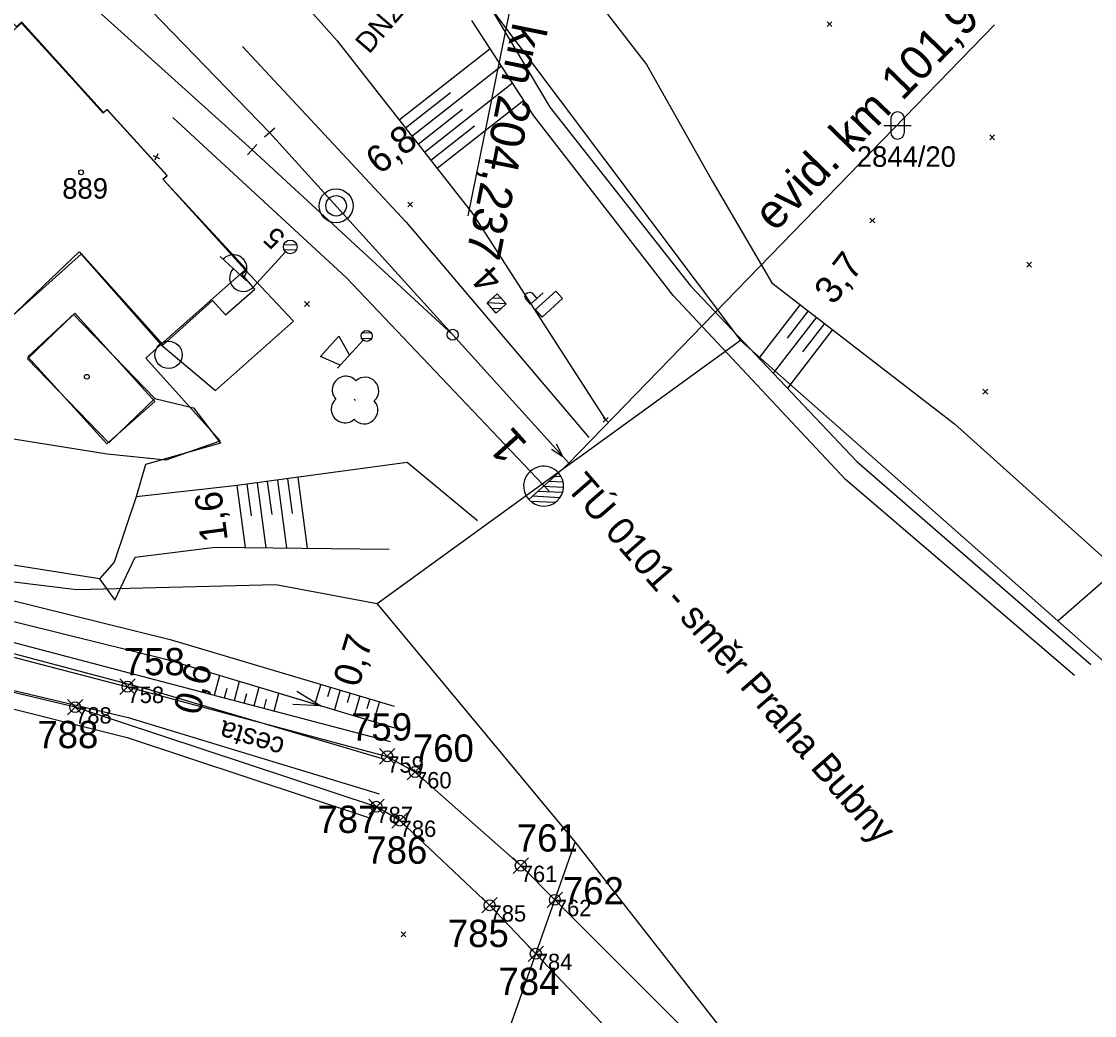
# Model space of a CAD drawing. Extents: x -800194 to -799078, y -1007177 to -1006597.
# Drawn here: x -799753.2 to -799674.6, y -1007080.7 to -1007007.9 of the extents above; entities that cross this region are included whole.
import ezdxf

# ---------------------------------------------------------------- set-up
doc = ezdxf.new("R2010")
doc.units = 0
for name, color, linetype in [('02_Osa_koleje', 7, 'Continuous'), ('_návrh', 7, 'Continuous'), ('Obvod stavby', 7, 'Continuous'), ('Vrstva 11', 7, 'Continuous'), ('Vrstva 13', 7, 'Continuous'), ('Vrstva 17', 7, 'Continuous'), ('Vrstva 2', 7, 'Continuous'), ('Vrstva 23', 7, 'Continuous'), ('Vrstva 25', 7, 'Continuous'), ('Vrstva 33', 7, 'Continuous'), ('Vrstva 4', 7, 'Continuous'), ('Vrstva 43', 7, 'Continuous'), ('Vrstva 48', 7, 'Continuous'), ('Vrstva 49', 7, 'Continuous'), ('Vrstva 5', 7, 'Continuous'), ('Vrstva 50', 7, 'Continuous'), ('Vrstva 51', 7, 'Continuous'), ('Vrstva 55', 7, 'Continuous'), ('Vrstva 56', 7, 'Continuous'), ('Vrstva 57', 7, 'Continuous'), ('Vrstva 58', 7, 'Continuous'), ('Vrstva 59', 7, 'Continuous'), ('Vrstva 60', 7, 'Continuous'), ('Vrstva 7', 7, 'Continuous')]:
    doc.layers.add(name, color=color, linetype=linetype)

msp = doc.modelspace()

# ---------------------------------------------------------------- linework, layer by layer
at = {"layer": '_návrh'}
for points in [[(-799821.595, -1006948.007), (-799811.064, -1006954.324), (-799803.753, -1006958.707), (-799793.935, -1006964.581), (-799784.224, -1006971.671), (-799782.913, -1006972.63), (-799767.418, -1006984.719), (-799752.333, -1006998.173), (-799735.027, -1007015.997), (-799721.623, -1007030.81), (-799713.555, -1007039.726), (-799713.111, -1007040.218)], [(-799820.755, -1006954.001), (-799803.004, -1006964.743), (-799786.682, -1006975.322), (-799769.882, -1006987.807), (-799754.745, -1007000.643), (-799736.311, -1007017.261), (-799721.623, -1007030.81)]]:
    msp.add_lwpolyline(points, dxfattribs=at)
at = {"layer": 'Obvod stavby'}
for p, q in [((-799746.003, -1007057.146), (-799744.871, -1007056.015)), ((-799746.003, -1007056.015), (-799744.871, -1007057.146)), ((-799749.839, -1007058.649), (-799748.707, -1007057.517)), ((-799749.839, -1007057.517), (-799748.707, -1007058.649)), ((-799726.983, -1007062.246), (-799725.851, -1007061.115)), ((-799726.983, -1007061.115), (-799725.851, -1007062.246)), ((-799724.949, -1007063.392), (-799723.818, -1007062.261)), ((-799724.949, -1007062.261), (-799723.818, -1007063.392)), ((-799727.776, -1007065.938), (-799726.645, -1007064.807)), ((-799727.776, -1007064.807), (-799726.645, -1007065.938)), ((-799726.072, -1007066.948), (-799724.941, -1007065.817)), ((-799726.072, -1007065.817), (-799724.941, -1007066.948)), ((-799717.202, -1007070.252), (-799716.071, -1007069.121)), ((-799717.202, -1007069.121), (-799716.071, -1007070.252)), ((-799719.487, -1007073.148), (-799718.356, -1007072.016)), ((-799719.487, -1007072.016), (-799718.356, -1007073.148)), ((-799714.706, -1007072.751), (-799713.575, -1007071.619)), ((-799714.706, -1007071.619), (-799713.575, -1007072.751)), ((-799716.104, -1007076.702), (-799714.973, -1007075.571)), ((-799716.104, -1007075.571), (-799714.973, -1007076.702))]:
    msp.add_line(p, q, dxfattribs=at)
for points in [[(-799715.538, -1007076.136), (-799718.921, -1007072.582), (-799725.506, -1007066.383), (-799727.21, -1007065.372), (-799749.273, -1007058.083), (-799778.375, -1007051.157), (-799786.694, -1007048.305), (-799789.278, -1007046.386), (-799797.841, -1007037.951)], [(-799788.573, -1007041.596), (-799787.358, -1007042.812), (-799784.876, -1007044.993), (-799778.248, -1007048.055), (-799745.437, -1007056.58), (-799726.417, -1007061.681), (-799724.384, -1007062.827), (-799716.636, -1007069.686), (-799714.141, -1007072.185)], [(-799715.538, -1007076.136), (-799696.398, -1007096.249), (-799680.349, -1007116.924), (-799673.33, -1007118.14), (-799693.106, -1007093.246), (-799714.141, -1007072.185)]]:
    msp.add_lwpolyline(points, dxfattribs=at)
for centre in [(-799745.437, -1007056.58), (-799749.273, -1007058.083), (-799726.417, -1007061.681), (-799724.384, -1007062.827), (-799727.21, -1007065.372), (-799725.506, -1007066.383), (-799716.636, -1007069.686), (-799714.141, -1007072.185), (-799718.921, -1007072.582), (-799715.538, -1007076.136)]:
    msp.add_circle(centre, 0.4, dxfattribs=at)
at = {"layer": 'Vrstva 11'}
for p, q in [((-799717.697, -1007028.557), (-799719.105, -1007028.487)), ((-799718.048, -1007028.164), (-799718.716, -1007028.131)), ((-799718.09, -1007028.913), (-799718.75, -1007028.88))]:
    msp.add_line(p, q, dxfattribs=at)
msp.add_lwpolyline([(-799718.436, -1007029.226), (-799719.107, -1007028.485), (-799718.366, -1007027.814), (-799717.695, -1007028.555)], close=True, dxfattribs=at)
at = {"layer": 'Vrstva 13'}
msp.add_line((-799737.018, -1007056.245), (-799731.272, -1007057.973), dxfattribs=at)
for points in [[(-799805.067, -1007021.457), (-799784.005, -1007043.381), (-799779.029, -1007045.556), (-799742.637, -1007054.554), (-799725.892, -1007059.592)], [(-799733.043, -1007056.918), (-799731.272, -1007057.973), (-799733.331, -1007057.876)]]:
    msp.add_lwpolyline(points, dxfattribs=at)
at = {"layer": 'Vrstva 17'}
msp.add_line((-799738.616, -1007038.761), (-799744.108, -1007040.301), dxfattribs=at)
for points in [[(-799828.95, -1007006.881), (-799820.579, -1007016.712), (-799786.808, -1007048.821), (-799777.641, -1007052.247), (-799745.452, -1007060.292), (-799727.709, -1007066.187)], [(-799744.108, -1007040.301), (-799744.795, -1007042.69), (-799746.422, -1007047.465), (-799747.487, -1007048.694), (-799771.226, -1007044.934), (-799785.53, -1007035.198), (-799789.014, -1007035.746), (-799804.246, -1007020.27), (-799801.55, -1007019.072), (-799803.933, -1007010.185)], [(-799743.447, -1007035.487), (-799740.602, -1007036.154), (-799738.616, -1007038.761)]]:
    msp.add_lwpolyline(points, dxfattribs=at)
at = {"layer": 'Vrstva 2'}
for p, q in [((-799713.111, -1007040.218), (-799681.94, -1007008.129)), ((-799735.398, -1007016.332), (-799734.656, -1007015.662)), ((-799735.972, -1007016.893), (-799736.65, -1007017.629)), ((-799713.88, -1007040.917), (-799713.111, -1007040.218)), ((-799716.05, -1007042.881), (-799713.879, -1007040.917)), ((-799713.668, -1007041.225), (-799714.191, -1007041.199)), ((-799713.508, -1007041.994), (-799714.989, -1007041.92)), ((-799713.532, -1007041.613), (-799714.59, -1007041.56)), ((-799716.05, -1007042.881), (-799716.05, -1007042.881)), ((-799713.772, -1007042.742), (-799715.786, -1007042.641)), ((-799713.582, -1007042.371), (-799715.388, -1007042.281)), ((-799714.138, -1007043.104), (-799715.906, -1007043.016))]:
    msp.add_line(p, q, dxfattribs=at)
msp.add_lwpolyline([(-799714.395, -1007039.183), (-799713.555, -1007039.726), (-799714.011, -1007038.836)], dxfattribs=at)
msp.add_circle((-799721.623, -1007030.81), 0.4, dxfattribs=at)
for centre, radius, start, end in [((-799714.965, -1007041.897), 1.462, 42.07181, 222.54133), ((-799714.964, -1007041.899), 1.464, 222.16134, 42.12219)]:
    msp.add_arc(centre, radius, start, end, dxfattribs=at)
at = {"layer": 'Vrstva 23'}
for points in [[(-799756.701, -1007031.945), (-799748.818, -1007024.882), (-799742.835, -1007031.56), (-799739.203, -1007028.306), (-799738.261, -1007029.357), (-799736.112, -1007027.467), (-799737.076, -1007026.37), (-799736.711, -1007026.049), (-799742.825, -1007019.446), (-799742.529, -1007019.177), (-799746.942, -1007014.309), (-799747.197, -1007014.54), (-799753.188, -1007007.931), (-799753.56, -1007008.268), (-799754.56, -1007007.163), (-799756.669, -1007009.071), (-799755.683, -1007010.172), (-799759.339, -1007013.448), (-799754.227, -1007019.154), (-799755.62, -1007020.402), (-799754.738, -1007021.386), (-799761.075, -1007027.063), (-799756.701, -1007031.945)], [(-799746.801, -1007038.734), (-799743.447, -1007035.487), (-799749.396, -1007029.332), (-799752.758, -1007032.581), (-799746.801, -1007038.734)]]:
    msp.add_lwpolyline(points, dxfattribs=at)
at = {"layer": 'Vrstva 25'}
for p, q in [((-799733.856, -1007024.746), (-799736.228, -1007027.319)), ((-799733.045, -1007024.219), (-799734.002, -1007024.258)), ((-799733.067, -1007024.595), (-799733.945, -1007024.63)), ((-799736.743, -1007026.845), (-799738.654, -1007025.083))]:
    msp.add_line(p, q, dxfattribs=at)
msp.add_circle((-799733.517, -1007024.378), 0.5, dxfattribs=at)
for centre, start, end in [((-799737.69, -1007025.955), 316.63315, 138.0383), ((-799736.963, -1007026.642), 137.33573, 317.33573)]:
    msp.add_arc(centre, 1, start, end, dxfattribs=at)
at = {"layer": 'Vrstva 33'}
for p, q in [((-799731.306, -1007032.395), (-799729.951, -1007030.925)), ((-799729.951, -1007030.925), (-799729.187, -1007032.309)), ((-799727.589, -1007030.677), (-799728.27, -1007030.705)), ((-799727.564, -1007031.076), (-799728.259, -1007031.105)), ((-799730.068, -1007033.265), (-799728.175, -1007031.207)), ((-799729.865, -1007033.044), (-799731.306, -1007032.395))]:
    msp.add_line(p, q, dxfattribs=at)
for points in [[(-799716.268, -1007028.193), (-799716.335, -1007028.041), (-799716.259, -1007027.823), (-799716.177, -1007027.748), (-799715.949, -1007027.691), (-799715.809, -1007027.778)], [(-799714.988, -1007027.738), (-799715.918, -1007028.58)], [(-799715.809, -1007027.778), (-799715.459, -1007028.164)], [(-799715.918, -1007028.58), (-799716.268, -1007028.193)]]:
    msp.add_lwpolyline(points, dxfattribs=at)
msp.add_lwpolyline([(-799715.065, -1007029.516), (-799715.565, -1007028.964), (-799714.071, -1007027.612), (-799713.571, -1007028.164)], close=True, dxfattribs=at)
msp.add_circle((-799727.921, -1007030.897), 0.401, dxfattribs=at)
at = {"layer": 'Vrstva 4'}
for points in [[(-799737.021, -1007009.695), (-799725.033, -1007022.564), (-799711.647, -1007038.333)], [(-799742.121, -1007014.91), (-799729.412, -1007026.634), (-799714.559, -1007042.274)]]:
    msp.add_lwpolyline(points, dxfattribs=at)
at = {"layer": 'Vrstva 43'}
msp.add_circle((-799742.428, -1007032.29), 1, dxfattribs=at)
at = {"layer": 'Vrstva 48'}
for p, q in [((-799725.544, -1007015.081), (-799718.879, -1007009.85)), ((-799724.618, -1007016.261), (-799718.059, -1007011.113)), ((-799725.081, -1007015.671), (-799721.775, -1007013.076)), ((-799723.692, -1007017.441), (-799717.239, -1007012.376)), ((-799722.766, -1007018.621), (-799716.419, -1007013.64)), ((-799724.155, -1007016.851), (-799720.902, -1007014.298)), ((-799723.229, -1007018.031), (-799720.029, -1007015.52)), ((-799696.174, -1007028.602), (-799699.202, -1007032.515)), ((-799694.987, -1007029.52), (-799698.156, -1007033.616)), ((-799695.58, -1007029.061), (-799697.13, -1007031.063)), ((-799694.394, -1007029.979), (-799696.014, -1007032.073)), ((-799693.801, -1007030.438), (-799697.111, -1007034.716)), ((-799733.719, -1007041.354), (-799733.377, -1007043.893)), ((-799732.976, -1007041.254), (-799732.276, -1007046.44)), ((-799737.435, -1007041.855), (-799736.824, -1007046.391)), ((-799736.692, -1007041.755), (-799736.379, -1007044.077)), ((-799735.949, -1007041.654), (-799735.308, -1007046.407)), ((-799735.205, -1007041.554), (-799734.878, -1007043.985)), ((-799734.462, -1007041.454), (-799733.792, -1007046.423)), ((-799739.057, -1007057.214), (-799738.671, -1007055.747)), ((-799737.607, -1007057.597), (-799737.233, -1007056.18)), ((-799738.332, -1007057.406), (-799738.142, -1007056.685)), ((-799736.882, -1007057.788), (-799736.698, -1007057.092)), ((-799736.157, -1007057.979), (-799735.796, -1007056.612)), ((-799734.706, -1007058.362), (-799734.359, -1007057.045)), ((-799731.291, -1007056.393), (-799731.721, -1007057.838)), ((-799730.573, -1007056.607), (-799730.788, -1007057.331)), ((-799729.854, -1007056.821), (-799730.285, -1007058.27)), ((-799729.135, -1007057.035), (-799729.351, -1007057.761)), ((-799735.431, -1007058.171), (-799735.254, -1007057.5)), ((-799728.416, -1007057.249), (-799728.849, -1007058.702)), ((-799727.697, -1007057.463), (-799727.914, -1007058.191)), ((-799726.978, -1007057.676), (-799727.412, -1007059.135))]:
    msp.add_line(p, q, dxfattribs=at)
at = {"layer": 'Vrstva 49'}
for p, q in [((-799694.208, -1007007.893), (-799693.854, -1007008.247)), ((-799694.208, -1007008.247), (-799693.854, -1007007.893)), ((-799682.293, -1007016.186), (-799681.939, -1007016.54)), ((-799682.293, -1007016.54), (-799681.939, -1007016.186)), ((-799743.554, -1007017.699), (-799743.098, -1007017.903)), ((-799743.224, -1007017.573), (-799743.428, -1007018.029)), ((-799724.92, -1007021.102), (-799724.566, -1007021.456)), ((-799724.92, -1007021.456), (-799724.566, -1007021.102)), ((-799720.161, -1007021.94), (-799710.424, -1007037.039)), ((-799691.067, -1007022.276), (-799690.713, -1007022.63)), ((-799691.067, -1007022.63), (-799690.713, -1007022.276)), ((-799679.586, -1007025.507), (-799679.232, -1007025.861)), ((-799679.586, -1007025.861), (-799679.232, -1007025.507)), ((-799732.468, -1007028.385), (-799732.114, -1007028.739)), ((-799732.468, -1007028.739), (-799732.114, -1007028.385)), ((-799682.799, -1007034.802), (-799682.445, -1007035.156)), ((-799682.799, -1007035.156), (-799682.445, -1007034.802)), ((-799710.601, -1007036.862), (-799710.247, -1007037.216)), ((-799710.601, -1007037.216), (-799710.247, -1007036.862)), ((-799725.405, -1007074.536), (-799725.051, -1007074.89)), ((-799725.405, -1007074.89), (-799725.051, -1007074.536))]:
    msp.add_line(p, q, dxfattribs=at)
for points in [[(-799823.433, -1006985.376), (-799817.838, -1006990.049), (-799815.5, -1006993.967), (-799810.13, -1006998.908), (-799803.933, -1007010.185), (-799801.55, -1007019.072), (-799804.246, -1007020.27), (-799789.014, -1007035.746), (-799784.101, -1007040.767), (-799778.537, -1007044.165), (-799742.314, -1007053.114), (-799725.901, -1007057.997)], [(-799823.433, -1006985.376), (-799822.824, -1006995.382), (-799809.853, -1007012.441), (-799805.067, -1007021.457), (-799784.005, -1007043.381), (-799779.029, -1007045.556), (-799742.637, -1007054.554), (-799725.892, -1007059.592)], [(-799822.824, -1006995.382), (-799817.689, -1007012.452), (-799816.629, -1007013.288), (-799784.593, -1007044.315), (-799779.066, -1007046.684), (-799743.002, -1007056.174), (-799726.202, -1007060.605)], [(-799716.248, -1006997.261), (-799711.439, -1007004.242), (-799711.113, -1007006.25), (-799707.442, -1007011.019), (-799702.585, -1007019.595), (-799698.243, -1007027.001), (-799684.872, -1007037.347), (-799668.902, -1007051.666)], [(-799733.039, -1007005.939), (-799730.086, -1007009.294), (-799720.161, -1007021.94)], [(-799718.907, -1007006.786), (-799714.515, -1007014.16), (-799704.214, -1007027.237), (-799692.017, -1007040.081), (-799674.887, -1007054.948)], [(-799676.078, -1007055.763), (-799692.866, -1007041.408), (-799705.479, -1007027.95), (-799715.681, -1007014.777), (-799720.214, -1007007.792)], [(-799719.795, -1007044.432), (-799724.968, -1007040.174), (-799737.6, -1007041.877), (-799744.795, -1007042.69), (-799746.422, -1007047.465), (-799747.487, -1007048.694), (-799746.374, -1007050.247)], [(-799746.374, -1007050.247), (-799744.874, -1007047.099), (-799739.015, -1007046.367), (-799726.285, -1007046.504)]]:
    msp.add_lwpolyline(points, dxfattribs=at)
at = {"layer": 'Vrstva 5'}
msp.add_line((-799720.48, -1007022.094), (-799714.568, -1006992.803), dxfattribs=at)
at = {"layer": 'Vrstva 50'}
msp.add_line((-799728.735, -1007035.635), (-799728.831, -1007035.529), dxfattribs=at)
for centre, start, end in [((-799729.448, -1007034.85), 42.14134, 222.14134), ((-799728.036, -1007034.921), 312.14134, 132.14134), ((-799729.519, -1007036.262), 132.14134, 312.14134), ((-799728.106, -1007036.333), 222.14134, 42.14134)]:
    msp.add_arc(centre, 1, start, end, dxfattribs=at)
at = {"layer": 'Vrstva 51'}
for points in [[(-799817.051, -1006918.973), (-799812.091, -1006931.542), (-799815.665, -1006943.128), (-799826.019, -1006959.481), (-799831.215, -1006965.513), (-799832.478, -1006972.309), (-799831.126, -1006986.858), (-799828.082, -1006983.271), (-799821.896, -1006976.034), (-799813.152, -1006974.923), (-799805.94, -1006982.791), (-799808.362, -1006984.771), (-799815.088, -1006977.554), (-799820.319, -1006978.428), (-799823.433, -1006985.376), (-799830.084, -1006997.726), (-799819.519, -1007011.695), (-799817.354, -1007013.08), (-799784.788, -1007044.956), (-799778.171, -1007047.694), (-799743.858, -1007056.783), (-799726.629, -1007061.89)], [(-799842.202, -1006982.511), (-799833.072, -1007000.361), (-799821.843, -1007014.249), (-799786.621, -1007048.212), (-799778.768, -1007050.961), (-799745.381, -1007058.848), (-799727.01, -1007064.42)]]:
    msp.add_lwpolyline(points, dxfattribs=at)
at = {"layer": 'Vrstva 55'}
for p, q in [((-799700.54, -1007031.23), (-799677.3, -1007051.77)), ((-799677.3, -1007051.77), (-799665.73, -1007041.59)), ((-799727.16, -1007050.52), (-799712.65, -1007067.97)), ((-799718.21, -1007083.69), (-799712.65, -1007067.97)), ((-799712.65, -1007067.97), (-799673.33, -1007118.14))]:
    msp.add_line(p, q, dxfattribs=at)
for points in [[(-799733.28, -1006992.13), (-799723.72, -1007000.38), (-799700.54, -1007031.23)], [(-799753.19, -1007008), (-799759.37, -1007013.49), (-799769.21, -1007022.23), (-799759.34, -1007033.19), (-799763.24, -1007036.79), (-799763.26, -1007036.9), (-799756.25, -1007038.04), (-799746.93, -1007039.54), (-799742.61, -1007039.98), (-799738.64, -1007038.58), (-799744.1, -1007032.52), (-799742.99, -1007031.53), (-799739, -1007034.9), (-799733.28, -1007029.82), (-799736.83, -1007026.06), (-799742.84, -1007019.43), (-799742.54, -1007019.16), (-799746.93, -1007014.32), (-799747.23, -1007014.58), (-799749.47, -1007012.1), (-799753.19, -1007008)], [(-799700.54, -1007031.23), (-799712.19, -1007039.67), (-799713.65, -1007040.73), (-799727.16, -1007050.52)], [(-799727.16, -1007050.52), (-799734.57, -1007049.13), (-799749.18, -1007049.49), (-799773.9, -1007046.46), (-799791.91, -1007040.49), (-799811.13, -1007032.26)], [(-799677.3, -1007051.77), (-799624.44, -1007098.49), (-799623.27, -1007096.82)]]:
    msp.add_lwpolyline(points, dxfattribs=at)
at = {"layer": 'Vrstva 56'}
for p, q in [((-799751.58, -1007027.23), (-799748.98, -1007024.74)), ((-799748.98, -1007024.74), (-799742.99, -1007031.53)), ((-799742.99, -1007031.53), (-799736.83, -1007026.06)), ((-799756.64, -1007032.07), (-799751.58, -1007027.23)), ((-799752.74, -1007032.43), (-799749.3, -1007029.24)), ((-799749.3, -1007029.24), (-799743.44, -1007035.69)), ((-799746.94, -1007038.81), (-799752.74, -1007032.43)), ((-799746.94, -1007038.81), (-799743.44, -1007035.69))]:
    msp.add_line(p, q, dxfattribs=at)
at = {"layer": 'Vrstva 58'}
for p, q in [((-799689.541, -1007014.991), (-799689.541, -1007015.992)), ((-799688.539, -1007015.992), (-799688.539, -1007014.991)), ((-799690.041, -1007015.491), (-799688.039, -1007015.491))]:
    msp.add_line(p, q, dxfattribs=at)
for centre, start, end in [((-799689.04, -1007014.991), 0, 180), ((-799689.04, -1007015.991), 180, 359.98789)]:
    msp.add_arc(centre, 0.5, start, end, dxfattribs=at)
at = {"layer": 'Vrstva 59'}
for centre in [(-799748.837, -1007018.919), (-799748.417, -1007033.889)]:
    msp.add_circle(centre, 0.175, dxfattribs=at)
at = {"layer": 'Vrstva 60'}
for p, q in [((-799745.437, -1007056.58), (-799745.437, -1007056.58)), ((-799749.273, -1007058.083), (-799749.273, -1007058.083)), ((-799726.417, -1007061.681), (-799726.417, -1007061.681)), ((-799724.384, -1007062.827), (-799724.384, -1007062.827)), ((-799727.21, -1007065.372), (-799727.21, -1007065.372)), ((-799725.506, -1007066.383), (-799725.506, -1007066.383)), ((-799716.636, -1007069.686), (-799716.636, -1007069.686)), ((-799718.921, -1007072.582), (-799718.921, -1007072.582)), ((-799714.141, -1007072.185), (-799714.141, -1007072.185)), ((-799715.538, -1007076.137), (-799715.538, -1007076.137))]:
    msp.add_line(p, q, dxfattribs=at)
at = {"layer": 'Vrstva 7'}
for radius in [1.246, 0.752]:
    msp.add_circle((-799730.163, -1007021.372), radius, dxfattribs=at)

# ---------------------------------------------------------------- texts
at = {"layer": '02_Osa_koleje'}
msp.add_text('TÚ 0101 - směr Praha Bubny', height=2, rotation=311.11703, dxfattribs=at).set_placement((-799713.38, -1007042.028))
at = {"layer": 'Obvod stavby'}
for s, p in [('758', (-799745.703, -1007055.745)), ('759', (-799729.063, -1007060.523)), ('788', (-799752.036, -1007061.083)), ('760', (-799724.536, -1007062.079)), ('787', (-799731.524, -1007067.291)), ('761', (-799716.924, -1007068.653)), ('786', (-799727.948, -1007069.545)), ('762', (-799713.551, -1007072.526)), ('785', (-799721.976, -1007075.646)), ('784', (-799718.268, -1007079.162))]:
    msp.add_text(s, height=2, rotation=360, dxfattribs=at).set_placement(p)
at = {"layer": 'Vrstva 11'}
msp.add_text('4', height=2, rotation=132.14163, dxfattribs=at).set_placement((-799717.855, -1007026.672))
at = {"layer": 'Vrstva 2'}
for s, rotation, p in [('evid. km 101,978', 45.83096, (-799698.03, -1007023.349)), ('1', 132.14177, (-799716.051, -1007038.832))]:
    msp.add_text(s, height=2.5, rotation=rotation, dxfattribs=at).set_placement(p)
at = {"layer": 'Vrstva 25'}
msp.add_text('5', height=1.5, rotation=137.33573, dxfattribs=at).set_placement((-799733.788, -1007023.566))
at = {"layer": 'Vrstva 43'}
msp.add_text('DN200', height=1.5, rotation=49.57522, dxfattribs=at).set_placement((-799727.74, -1007010.31))
at = {"layer": 'Vrstva 48'}
for s, rotation, p in [('6,8', 38.126, (-799726.984, -1007019.147)), ('3,7', 52.26858, (-799693.728, -1007028.703)), ('1,6', 97.67811, (-799738.081, -1007045.849)), ('0,7', 73.43183, (-799728.505, -1007056.697)), ('0,6', 75.22471, (-799740.162, -1007058.754))]:
    msp.add_text(s, height=2, rotation=rotation, dxfattribs=at).set_placement(p)
at = {"layer": 'Vrstva 5'}
msp.add_text('km 204,237', height=2.5, rotation=258.58947, dxfattribs=at).set_placement((-799717.203, -1007007.869))
at = {"layer": 'Vrstva 51'}
msp.add_text('cesta', height=1.5, rotation=163.12723, dxfattribs=at).set_placement((-799733.835, -1007060.41))
at = {"layer": 'Vrstva 57'}
for s, p in [('2844/20', (-799692.023, -1007018.517)), ('889', (-799750.215, -1007020.847))]:
    msp.add_text(s, height=1.5, dxfattribs=at).set_placement(p)
at = {"layer": 'Vrstva 60'}
for s, p in [('758', (-799745.437, -1007057.78)), ('788', (-799749.273, -1007059.283)), ('759', (-799726.417, -1007062.881)), ('760', (-799724.384, -1007064.027)), ('787', (-799727.21, -1007066.572)), ('786', (-799725.506, -1007067.583)), ('761', (-799716.636, -1007070.886)), ('785', (-799718.921, -1007073.782)), ('762', (-799714.141, -1007073.385)), ('784', (-799715.538, -1007077.337))]:
    msp.add_text(s, height=1.2, dxfattribs=at).set_placement(p)

doc.saveas('drawing.dxf')
